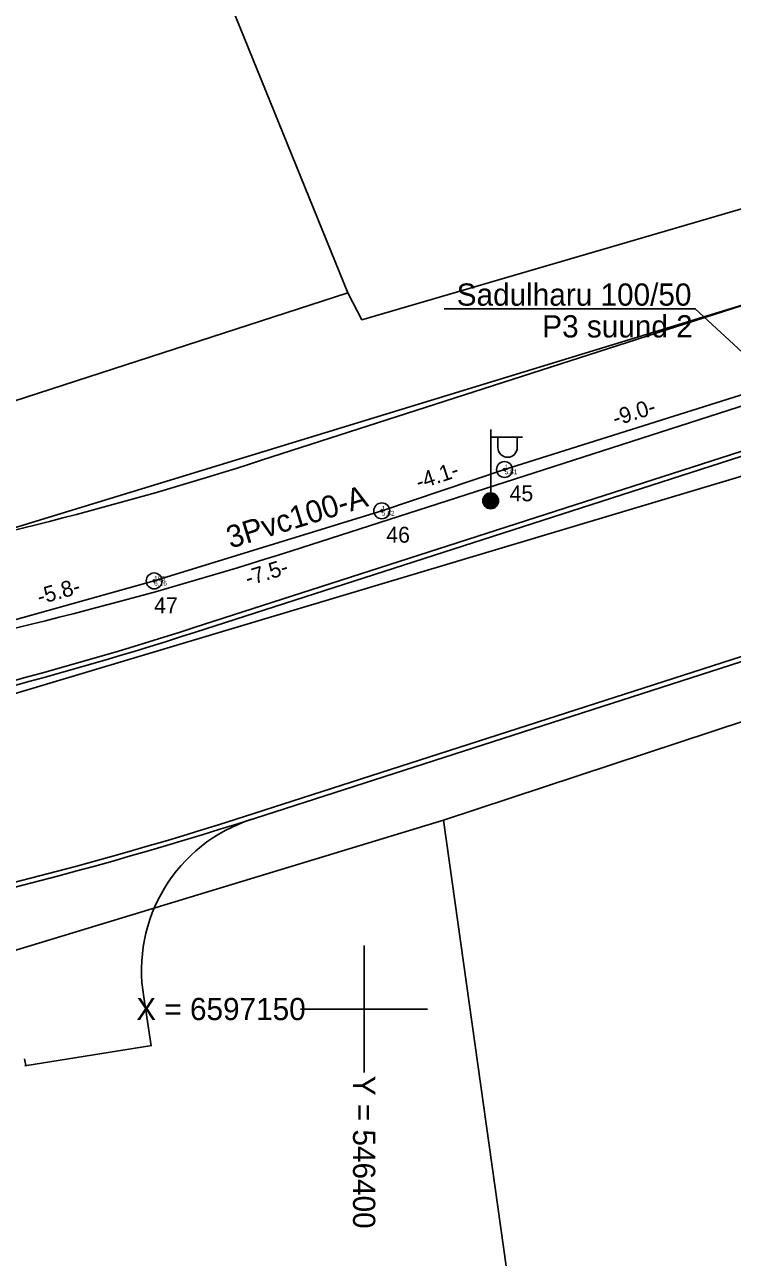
# Model space of a CAD drawing. Extents: x 546339 to 546593, y 6597108 to 6597251.
# Drawn here: x 546389.31 to 546411.59, y 6597142.18 to 6597180.99 of the extents above; entities that cross this region are included whole.
import ezdxf

# ---------------------------------------------------------------- set-up
doc = ezdxf.new("R2010")
doc.units = 0
for name, color, linetype in [('JOONSIDE', 7, 'Continuous'), ('KOORDPUNKT', 7, 'Continuous'), ('MOOTKORG-EH2000', 7, 'Continuous'), ('MOOTMPUNKT', 7, 'Continuous'), ('MOOTNR', 7, 'Continuous'), ('MOOTPIIR', 7, 'Continuous'), ('PIIR', 7, 'Continuous'), ('POST', 7, 'Continuous'), ('SITRASS', 7, 'Continuous'), ('TEE', 7, 'Continuous'), ('VORK', 7, 'Continuous')]:
    doc.layers.add(name, color=color, linetype=linetype)

msp = doc.modelspace()

# ---------------------------------------------------------------- linework, layer by layer
at = {"layer": 'KOORDPUNKT'}
for centre, radius in [((546404.421, 6597166.986), 0.25), ((546404.421, 6597166.986), 0.025), ((546404.421, 6597166.986), 0.0221), ((546404.421, 6597166.986), 0.0191), ((546404.421, 6597166.986), 0.0161), ((546404.421, 6597166.986), 0.0132), ((546404.421, 6597166.986), 0.0102), ((546404.421, 6597166.986), 0.00726), ((546404.421, 6597166.986), 0.0043), ((546400.555, 6597165.683), 0.25), ((546400.555, 6597165.683), 0.025), ((546400.555, 6597165.683), 0.0221), ((546400.555, 6597165.683), 0.0191), ((546400.555, 6597165.683), 0.0161), ((546400.555, 6597165.683), 0.0132), ((546400.555, 6597165.683), 0.0102), ((546400.555, 6597165.683), 0.00726), ((546400.555, 6597165.683), 0.0043), ((546393.387, 6597163.477), 0.25), ((546393.387, 6597163.477), 0.025), ((546393.387, 6597163.477), 0.0221), ((546393.387, 6597163.477), 0.0191), ((546393.387, 6597163.477), 0.0161), ((546393.387, 6597163.477), 0.0132), ((546393.387, 6597163.477), 0.0102), ((546393.387, 6597163.477), 0.00726), ((546393.387, 6597163.477), 0.0043)]:
    msp.add_circle(centre, radius, dxfattribs=at)
at = {"layer": 'MOOTMPUNKT'}
for centre in [(546404.421, 6597166.986), (546400.555, 6597165.683), (546393.387, 6597163.477)]:
    msp.add_circle(centre, 0.03, dxfattribs=at)
at = {"layer": 'MOOTPIIR'}
msp.add_lwpolyline([(546443.888, 6597176.348), (546374.62, 6597155.63), (546372.739, 6597147.606), (546361.644, 6597146.697), (546361.895, 6597151.274), (546368.79, 6597152.088), (546371.486, 6597159.799), (546428.467, 6597177.226), (546428.906, 6597181.927), (546431.038, 6597182.742), (546435.363, 6597179.169)], dxfattribs=at)
at = {"layer": 'PIIR'}
for points in [[(546510.07, 6597205.36), (546491.04, 6597199.45), (546466.79, 6597191.98), (546431.99, 6597181.07), (546399.93, 6597171.7), (546399.49, 6597172.55), (546362.07, 6597160.42), (546350.54, 6597167.22), (546341.457, 6597167.537)], [(546392.84, 6597188.911), (546399.49, 6597172.55), (546399.93, 6597171.7), (546431.99, 6597181.07), (546424.887, 6597197.926)], [(546356.198, 6597174.862), (546362.07, 6597160.42), (546399.49, 6597172.55), (546392.84, 6597188.911)], [(546339.379, 6597150.424), (546339.82, 6597150.4), (546343.3, 6597148.09), (546350.66, 6597143.2), (546387.61, 6597151.42), (546402.5, 6597155.95), (546434.27, 6597166.43), (546452.55, 6597172.32), (546467.66, 6597177.18), (546479.16, 6597180.72), (546505.65, 6597188.82)], [(546437.756, 6597143.407), (546434.27, 6597166.43), (546402.5, 6597155.95), (546405.647, 6597133.544)], [(546405.647, 6597133.544), (546402.5, 6597155.95), (546387.61, 6597151.42), (546350.66, 6597143.2), (546352.148, 6597127.926)]]:
    msp.add_lwpolyline(points, dxfattribs=at)
at = {"layer": 'POST'}
for p, q in [((546403.984, 6597166.249), (546403.984, 6597168.249)), ((546403.984, 6597167.999), (546404.984, 6597167.999)), ((546404.211, 6597167.678), (546404.211, 6597167.999)), ((546404.823, 6597167.678), (546404.823, 6597167.999)), ((546403.984, 6597165.999), (546403.984, 6597165.999))]:
    msp.add_line(p, q, dxfattribs=at)
for radius in [0.25, 0.225, 0.2, 0.175, 0.15, 0.125, 0.1, 0.075, 0.05, 0.025]:
    msp.add_circle((546403.984, 6597165.999), radius, dxfattribs=at)
msp.add_arc((546404.517, 6597167.678), 0.306, 180, 0, dxfattribs=at)
at = {"layer": 'SITRASS'}
for points in [[(546412.984, 6597169.682), (546410.424, 6597172.044), (546402.523, 6597172.044)], [(546412.984, 6597169.682), (546404.421, 6597166.986), (546400.555, 6597165.683), (546393.387, 6597163.477), (546387.753, 6597161.903), (546381.148, 6597160.525), (546374.997, 6597158.932), (546372.419, 6597157.971), (546371.306, 6597154.04), (546370.157, 6597150.238), (546369.857, 6597149.704), (546369.198, 6597149.563), (546364.495, 6597149.159), (546363.925, 6597149.09)]]:
    msp.add_lwpolyline(points, dxfattribs=at)
at = {"layer": 'TEE'}
for p, q in [((546518.272, 6597195.197), (546396.577, 6597156.011)), ((546394.646, 6597162.008), (546437.58, 6597175.833)), ((546437.484, 6597175.644), (546394.692, 6597161.865)), ((546396.577, 6597156.011), (546396.577, 6597156.011)), ((546393.295, 6597148.843), (546393.06, 6597150.373)), ((546389.32, 6597148.214), (546393.32, 6597148.847)), ((546389.31, 6597148.436), (546389.345, 6597148.218))]:
    msp.add_line(p, q, dxfattribs=at)
for points in [[(546514.456, 6597205.157), (546396.804, 6597167.285), (546396.804, 6597167.285)], [(546515.375, 6597202.301), (546397.724, 6597164.429), (546397.724, 6597164.429)], [(546396.531, 6597156.154), (546518.226, 6597195.34), (546518.226, 6597195.34)]]:
    msp.add_lwpolyline(points, dxfattribs=at)
for centre, radius, start, end in [((546362.026, 6597275.325), 113.5, 280.79026, 287.8433), ((546362.026, 6597275.325), 116.5, 280.79026, 287.8433), ((546358.831, 6597273.234), 116.85, 272.25054, 287.8487), ((546358.831, 6597273.234), 117, 272.25054, 287.8487), ((546358.831, 6597273.234), 123, 270.39825, 287.8487), ((546358.831, 6597273.234), 123.15, 270.39825, 287.8487), ((546397.989, 6597151.212), 5, 107.7458, 189.667)]:
    msp.add_arc(centre, radius, start, end, dxfattribs=at)
at = {"layer": 'VORK'}
for p, q in [((546400, 6597152), (546400, 6597148)), ((546398, 6597150), (546402, 6597150))]:
    msp.add_line(p, q, dxfattribs=at)

# ---------------------------------------------------------------- texts
at = {"layer": 'JOONSIDE'}
for s, rotation, p in [('-9.0-', 17.4713, (546407.912, 6597168.347)), ('-4.1-', 18.6306, (546401.721, 6597166.34)), ('-7.5-', 17.1054, (546396.339, 6597163.309)), ('-5.8-', 15.6116, (546389.78, 6597162.729))]:
    msp.add_text(s, height=0.5, rotation=rotation, dxfattribs=at).set_placement(p)
at = {"layer": 'KOORDPUNKT'}
for s, p in [('45', (546404.58, 6597165.984)), ('46', (546400.698, 6597164.681)), ('47', (546393.387, 6597162.459))]:
    msp.add_text(s, height=0.5, dxfattribs=at).set_placement(p)
at = {"layer": 'MOOTKORG-EH2000'}
for s, p in [('5.81', (546404.421, 6597166.836)), ('5.82', (546400.555, 6597165.533)), ('6.16', (546393.387, 6597163.327))]:
    msp.add_text(s, height=0.15, dxfattribs=at).set_placement(p)
at = {"layer": 'MOOTNR'}
for s, p in [('1', (546404.421, 6597166.986)), ('1', (546400.555, 6597165.683)), ('100', (546393.387, 6597163.477))]:
    msp.add_text(s, height=0.15, dxfattribs=at).set_placement(p)
at = {"layer": 'SITRASS'}
for s, p in [('Sadulharu 100/50', (546402.915, 6597172.142)), ('P3 suund 2', (546405.609, 6597171.142))]:
    msp.add_text(s, height=0.7, dxfattribs=at).set_placement(p)
msp.add_text('3Pvc100-A', height=0.7, rotation=17.1054, dxfattribs=at).set_placement((546395.792, 6597164.492))
at = {"layer": 'VORK'}
msp.add_text('X = 6597150', height=0.7, dxfattribs=at).set_placement((546392.825, 6597149.65))
msp.add_text('Y = 546400 ', height=0.7, rotation=270, dxfattribs=at).set_placement((546399.65, 6597147.9))

doc.saveas('drawing.dxf')
